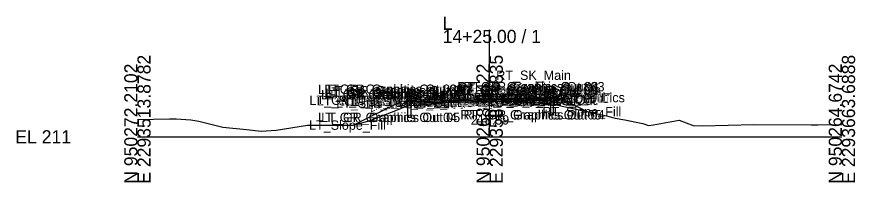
# Model space of a CAD drawing. Extents: x -26 to 7053, y -10 to 7035.
# Drawn here: x -25.7 to 152.8, y 4490.3 to 4525.6 of the extents above; entities that cross this region are included whole.
import ezdxf

# ---------------------------------------------------------------- set-up
doc = ezdxf.new("R2010")
doc.units = 0
for name, color, linetype in [('Default', 7, 'Continuous'), ('Exist Cross Section Cell', 7, 'Continuous'), ('Exist XS Center Line Elevation Label', 7, 'Continuous'), ('Exist XS Ground Line', 7, 'Continuous'), ('Prop CMT Guardrail Graphics', 7, 'Continuous'), ('Prop CMT Pvmt Course 1', 7, 'Continuous'), ('Prop CMT Pvmt Course 2', 7, 'Continuous'), ('Prop CMT Pvmt Surface', 7, 'Continuous'), ('Prop CMT Pvmt Surface Overlay', 7, 'Continuous'), ('Prop CMT Pvmt Surface Shoulder', 7, 'Continuous'), ('Prop CMT Shld Paved Course 1', 7, 'Continuous'), ('Prop CMT Shld Paved Course 2', 7, 'Continuous'), ('Prop CMT Slope Grass', 7, 'Continuous'), ('Prop CMT Subgrade Earthwork', 7, 'Continuous'), ('Prop XS EOT Tick Mark', 7, 'Continuous'), ('Prop XS SE Text', 7, 'Continuous'), ('Prop XS Side Slope Text', 7, 'Continuous')]:
    doc.layers.add(name, color=color, linetype=linetype)

msp = doc.modelspace()

# ---------------------------------------------------------------- linework, layer by layer
at = {"layer": 'Exist Cross Section Cell'}
for p, q in [((75, 4500), (75, 4522.8)), ((0, 4500), (75, 4500)), ((75, 4500), (150, 4500))]:
    msp.add_line(p, q, dxfattribs=at)
at = {"layer": 'Exist XS Ground Line'}
for p, q in [((55.4, 4505.73), (57.4, 4506.58)), ((57.4, 4506.58), (60.44, 4506.85)), ((60.44, 4506.85), (67.21, 4507.47)), ((67.21, 4507.47), (71.26, 4507.53)), ((71.26, 4507.53), (75, 4507.59)), ((75, 4507.59), (75.36, 4507.6)), ((75.36, 4507.6), (77, 4507.55)), ((77, 4507.55), (83.1, 4507.43)), ((83.1, 4507.43), (86.07, 4507.16)), ((86.07, 4507.16), (88.51, 4506.94)), ((88.51, 4506.94), (99.91, 4504.45)), ((49.34, 4503.37), (55.4, 4505.73)), ((99.91, 4504.45), (100.38, 4504.34)), ((0, 4503.72), (6.82, 4503.84)), ((6.82, 4503.84), (7.74, 4503.81)), ((7.74, 4503.81), (8.24, 4503.81)), ((8.24, 4503.81), (11.36, 4503.59)), ((11.36, 4503.59), (13.09, 4503.36)), ((13.09, 4503.36), (18.15, 4502.08)), ((45.96, 4502.47), (49.34, 4503.37)), ((100.38, 4504.34), (101.7, 4504)), ((101.7, 4504), (103.78, 4503.65)), ((103.78, 4503.65), (107.6, 4502.8)), ((107.6, 4502.8), (108.81, 4502.39)), ((109.86, 4502.58), (115.38, 4503.53)), ((115.38, 4503.53), (118.3, 4502.38)), ((120.29, 4502.36), (131.24, 4502.63)), ((131.24, 4502.63), (143.44, 4502.52)), ((144.88, 4502.53), (150, 4502.61)), ((18.15, 4502.08), (23.22, 4501.52)), ((23.22, 4501.52), (26.33, 4501.22)), ((26.33, 4501.22), (29.52, 4501.41)), ((29.52, 4501.41), (36.18, 4502.45)), ((36.18, 4502.45), (45.96, 4502.47)), ((108.81, 4502.39), (109.86, 4502.58)), ((118.3, 4502.38), (120.29, 4502.36)), ((143.44, 4502.52), (144.88, 4502.53))]:
    msp.add_line(p, q, dxfattribs=at)
at = {"layer": 'Prop CMT Guardrail Graphics'}
for points in [[(57.57, 4504.14), (57.57, 4510.14)], [(57.57, 4510.14), (58.91, 4510.14), (59.18, 4509.84)], [(59.18, 4509.84), (58.91, 4509.55)], [(88.59, 4510.69), (87.26, 4510.69), (86.99, 4510.4)], [(86.99, 4510.4), (87.26, 4510.11)], [(87.26, 4510.11), (86.99, 4509.82)], [(86.99, 4509.82), (87.26, 4509.53), (87.93, 4509.53)], [(88.59, 4504.69), (88.59, 4510.69)], [(59.18, 4509.26), (58.91, 4508.97), (58.24, 4508.97)], [(58.24, 4508.97), (58.24, 4504.14)], [(58.91, 4509.55), (59.18, 4509.26)], [(87.93, 4509.53), (87.93, 4504.69)], [(87.93, 4504.69), (88.59, 4504.69)], [(58.24, 4504.14), (57.57, 4504.14)]]:
    msp.add_lwpolyline(points, dxfattribs=at)
at = {"layer": 'Prop CMT Pvmt Course 1'}
for points in [[(75, 4508.12), (65, 4507.92)], [(75, 4508.12), (85, 4508.32)], [(75, 4508), (75, 4508.12)], [(75, 4508), (75, 4508.12)], [(85, 4508.07), (75, 4507.87)], [(75, 4507.87), (75, 4508), (75, 4508)], [(75, 4507.87), (75, 4508), (75, 4508)], [(85, 4508.32), (85, 4508.07)], [(65, 4507.92), (65, 4507.67)], [(65, 4507.67), (75, 4507.87)]]:
    msp.add_lwpolyline(points, dxfattribs=at)
at = {"layer": 'Prop CMT Pvmt Course 2'}
for points in [[(75, 4507.87), (85, 4508.07)], [(85, 4508.07), (85, 4507.74)], [(75, 4507.87), (65, 4507.67)], [(65, 4507.67), (65, 4507.34)], [(65, 4507.34), (75, 4507.54)], [(75, 4507.54), (75, 4507.87)], [(75, 4507.54), (75, 4507.87)], [(85, 4507.74), (75, 4507.54)]]:
    msp.add_lwpolyline(points, dxfattribs=at)
at = {"layer": 'Prop CMT Pvmt Surface'}
for points in [[(75, 4508.12), (65, 4507.92)], [(75, 4508.12), (85, 4508.32)]]:
    msp.add_lwpolyline(points, dxfattribs=at)
at = {"layer": 'Prop CMT Pvmt Surface Overlay'}
for points in [[(75, 4508.12), (65, 4507.92)], [(75, 4508.12), (85, 4508.32)]]:
    msp.add_lwpolyline(points, dxfattribs=at)
at = {"layer": 'Prop CMT Pvmt Surface Shoulder'}
for points in [[(85, 4508.32), (86.98, 4508.36)], [(65, 4507.92), (59.2, 4507.8)]]:
    msp.add_lwpolyline(points, dxfattribs=at)
at = {"layer": 'Prop CMT Shld Paved Course 1'}
for points in [[(85, 4508.32), (86.98, 4508.36), (87.23, 4508.12)], [(85, 4508.07), (85, 4508.32)], [(87.23, 4508.12), (85, 4508.07)], [(65, 4507.92), (59.2, 4507.8), (58.95, 4507.55)], [(58.95, 4507.55), (65, 4507.67)], [(65, 4507.67), (65, 4507.92)]]:
    msp.add_lwpolyline(points, dxfattribs=at)
at = {"layer": 'Prop CMT Shld Paved Course 2'}
for points in [[(85, 4508.07), (87.23, 4508.12), (87.73, 4508.13), (88.05, 4507.8)], [(85, 4507.74), (85, 4508.07)], [(65, 4507.67), (58.95, 4507.55), (58.45, 4507.54), (58.11, 4507.2)], [(58.11, 4507.2), (65, 4507.34)], [(65, 4507.34), (65, 4507.67)], [(88.05, 4507.8), (85, 4507.74)]]:
    msp.add_lwpolyline(points, dxfattribs=at)
at = {"layer": 'Prop CMT Slope Grass'}
for points in [[(86.98, 4508.36), (86.99, 4508.36)], [(86.99, 4508.36), (89.99, 4508.24)], [(89.99, 4508.24), (95.76, 4505.36)], [(56.18, 4507.56), (46.02, 4502.49)], [(59.18, 4507.8), (56.18, 4507.56)], [(59.2, 4507.8), (59.18, 4507.8)]]:
    msp.add_lwpolyline(points, dxfattribs=at)
at = {"layer": 'Prop CMT Subgrade Earthwork'}
for points in [[(88.05, 4507.8), (88.55, 4508.3)], [(58.11, 4507.2), (57.63, 4507.68)], [(65, 4507.34), (58.11, 4507.2)], [(75, 4507.54), (65, 4507.34)], [(75, 4507.54), (85, 4507.74)], [(85, 4507.74), (88.05, 4507.8)]]:
    msp.add_lwpolyline(points, dxfattribs=at)
at = {"layer": 'Prop XS EOT Tick Mark'}
for p, q in [((65, 4507.92), (65, 4509.83)), ((85, 4508.32), (85, 4510.23))]:
    msp.add_line(p, q, dxfattribs=at)

# ---------------------------------------------------------------- texts
at = {"layer": 'Default'}
for s, height, p in [('RT_SK_Main', 2, (76.4, 4512.12)), ('RT_GR_Graphics Out 02', 2, (68.11, 4509.69)), ('RT_GR_Graphics Out 03', 2, (69.44, 4509.69)), ('LT_GR_Graphics Out 03', 2, (38.47, 4509.14)), ('LT_GR_Graphics Out 06', 2, (39.09, 4507.97)), ('LT_GR_Graphics Out 02', 2, (39.8, 4509.14)), ('LT_GR_Graphics Out 09', 2, (39.8, 4508.55)), ('LT_GR_Graphics Out 07', 2, (39.8, 4507.97)), ('LT_GR_Graphics Out 08', 2, (40.07, 4508.26)), ('LT_GR_Graphics Out 01', 2, (40.64, 4508.84)), ('LT_TM_OEOT', 2, (57.94, 4507.96)), ('RT_GR_Graphics Out 08', 2, (67.84, 4508.82)), ('RT_GR_Graphics Out 09', 2, (68.11, 4509.11)), ('RT_GR_Graphics Out 07', 2, (68.11, 4508.53)), ('RT_GR_Graphics Out 01', 2, (68.41, 4509.4)), ('RT_GR_Graphics Out 06', 2, (68.73, 4508.53)), ('RT_TM_OEOT', 2, (73.9, 4508.28)), ('LT_GS_OS_GR_Face_Graphics', 2, (36.63, 4506.8)), ('LT_Sub_Trench_Out_DLT', 2, (38.19, 4506.68)), ('LT_Sub_Trench_Out', 2, (42.31, 4506.2)), ('LT_PS2_Shelf_Out', 2, (44.43, 4506.54)), ('LT_GS_OS_CTL', 2, (45.55, 4506.56)), ('LT_PS2_OEOP', 2, (49.18, 4506.55)), ('LT_PS1_OEOP', 2, (50.01, 4506.8)), ('LT_Sub_OEOT', 2, (55.08, 4506.34)), ('LT_PV2_OEOT', 2, (55.17, 4506.67)), ('LT_PV1_OEOT', 2, (55.74, 4506.92)), ('RT_PV1_OEEOP_W', 2, (62.94, 4507)), ('LT_PV1_OEEOP_W', 2, (62.98, 4507)), ('RT_Sub_OEEOP', 2, (64.17, 4506.54)), ('LT_Sub_OEEOP', 2, (64.21, 4506.54)), ('RT_PV2_OEEOP', 2, (64.26, 4506.87)), ('LT_PV2_OEEOP', 2, (64.31, 4506.87)), ('RT_GS_OS_GR_Face_Graphics', 2, (64.4, 4507.36)), ('PV1_PGL_W', 2, (67.58, 4507)), ('RT_Sub_Trench_Out_DLT', 2, (69.07, 4507.3)), ('PV1_PGL', 2, (69.47, 4507.12)), ('RT_Sub_Trench_Out', 2, (72.21, 4506.8)), ('RT_PS2_Shelf_Out', 2, (73.66, 4507.13)), ('RT_Sub_OEOT', 2, (75.03, 4506.74)), ('RT_PV2_OEOT', 2, (75.13, 4507.07)), ('RT_PV1_OEOT', 2, (75.69, 4507.32)), ('RT_PS2_OEOP', 2, (77.41, 4507.12)), ('RT_PS1_OEOP', 2, (77.74, 4507.36)), ('RT_GS_OS_CTL', 2, (79.31, 4507.24)), ('RT_Slope_Fill', 2, (86.23, 4504.36)), ('LT_GR_Graphics Out 04', 2, (38.47, 4503.14)), ('LT_GR_Graphics Out 05', 2, (39.14, 4503.14)), ('RT_GR_Graphics Out 05', 2, (68.78, 4503.69)), ('RT_GR_Graphics Out 04', 2, (69.44, 4503.69)), ('LT_Slope_Fill', 2, (36.54, 4501.49)), ('-', 0.0001, (0, 4500))]:
    msp.add_text(s, height=height, dxfattribs=at).set_placement(p)
at = {"layer": 'Exist Cross Section Cell'}
for s, p in [('L', (65, 4522.8)), ('14+25.00 / 1', (65, 4520)), ('EL 211', (-26, 4498.6))]:
    msp.add_text(s, height=2.8, dxfattribs=at).set_placement(p)
for s, p in [('E 2293513.8782', (2.8, 4490)), ('E 2293588.7835', (77.8, 4490)), ('E 2293663.6888', (152.8, 4490)), ('N 950272.2102', (0, 4490)), ('N 950268.4422', (75, 4490)), ('N 950264.6742', (150, 4490))]:
    msp.add_text(s, height=2.8, rotation=90, dxfattribs=at).set_placement(p)
at = {"layer": 'Exist XS Center Line Elevation Label'}
msp.add_text('218.59', height=2, dxfattribs=at).set_placement((70.97, 4502.59))
at = {"layer": 'Prop XS SE Text'}
for p in [(67.36, 4508.97), (77.36, 4509.17)]:
    msp.add_text('0.020', height=1.5, rotation=1.1458, dxfattribs=at).set_placement(p)
at = {"layer": 'Prop XS Side Slope Text'}
for rotation, p in [(333.4349, (92.14, 4508)), (26.5651, (49.7, 4505.16))]:
    msp.add_text('2:1', height=1.5, rotation=rotation, dxfattribs=at).set_placement(p)

doc.saveas('drawing.dxf')
